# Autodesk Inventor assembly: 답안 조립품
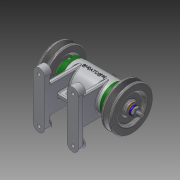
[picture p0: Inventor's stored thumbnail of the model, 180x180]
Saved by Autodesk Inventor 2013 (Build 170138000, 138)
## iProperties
Created: 2015-11
Part Number: 답안 조립품
Document SubType Name: Assembly
Designer: Administrator
Author: Administrator
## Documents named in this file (15)
- C:\Documents and Settings\Administrator\바탕 화면\451110v1009\답안 조립품.iam
- C:\Documents and Settings\Administrator\바탕 화면\451110v1009\1-본체.ipt
- C:\Documents and Settings\Administrator\바탕 화면\451110v1009\니플 M 6 x 0.75.ipt
- C:\Documents and Settings\Administrator\바탕 화면\451110v1009\와셔 6x11.5.ipt
- C:\Documents and Settings\Administrator\바탕 화면\451110v1009\볼트 M 6 x 8.ipt
- C:\Documents and Settings\Administrator\바탕 화면\451110v1009\축.ipt
- C:\Documents and Settings\Administrator\바탕 화면\451110v1009\베어링 15 x 32 x 9.ipt
- C:\Documents and Settings\Administrator\바탕 화면\451110v1009\오일 실 15 25 7.ipt
- C:\Documents and Settings\Administrator\바탕 화면\451110v1009\볼트 M4 x 12.ipt
- C:\Documents and Settings\Administrator\바탕 화면\451110v1009\커버.ipt
- C:\Documents and Settings\Administrator\바탕 화면\451110v1009\키 3 x 3 x 12.ipt
- C:\Documents and Settings\Administrator\바탕 화면\451110v1009\V벨트풀리.ipt
- C:\Documents and Settings\Administrator\바탕 화면\451110v1009\와셔 8x17.ipt
- C:\Documents and Settings\Administrator\바탕 화면\451110v1009\스프링와셔 8.ipt
- C:\Documents and Settings\Administrator\바탕 화면\451110v1009\너트 M 8.ipt
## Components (13 placed, 4 different names)
1. 1-본체:1
2. KS B 2023 6002 - 15 x 32 x 9:1
3. KS B 2023 6002 - 15 x 32 x 9:2
4. V벨트풀리:1
5. V벨트풀리:2
6. ISO 4762 M4 x 12:2
7. ISO 4762 M4 x 12:3
8. ISO 4762 M4 x 12:4
9. ISO 4762 M4 x 12:5
10. ISO 4762 M4 x 12:1
11. ISO 4762 M4 x 12:6
12. ISO 4762 M4 x 12:7
13. ISO 4762 M4 x 12:8
